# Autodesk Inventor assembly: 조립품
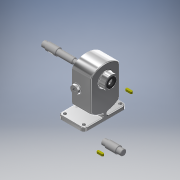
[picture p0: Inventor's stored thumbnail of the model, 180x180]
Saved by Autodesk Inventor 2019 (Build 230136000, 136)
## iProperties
Created: 2019-03
Part Number: 조립품
Material: 일반
Document SubType Name: Assembly
Designer: User
Author: User
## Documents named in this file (6)
- C:\Users\User\Desktop\490307V1016\조립품.iam
- C:\Users\User\Desktop\490307V1016\본체.ipt
- C:\Users\User\Desktop\490307V1016\메인축.ipt
- C:\Users\User\Desktop\490307V1016\오일 실 16 28 7.ipt
- C:\Users\User\Desktop\490307V1016\키 6 x 6 x 18.ipt
- C:\Users\User\Desktop\490307V1016\서브축.ipt
